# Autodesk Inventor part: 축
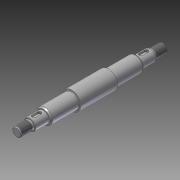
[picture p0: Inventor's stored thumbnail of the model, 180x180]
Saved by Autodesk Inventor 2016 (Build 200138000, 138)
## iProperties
Created: 2018-11
Part Number: 축
Material: 강철, 연강
Document SubType Name: Modeling
Designer: mduedu
Density: 1 g/cm^3
Appearance: 강철
Author: mduedu
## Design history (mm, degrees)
sketch "스케치1"
  geometry: L1 (-24, 0)-(24, 0); L2 (24, 0)-(24, 12); L3 (24, 12)-(-24, 12); L4 (-24, 12)-(-24, 0); L5 (-24, 0)-(-79, 0); L6 (-79, 0)-(-79, 7.5); L7 (-79, 7.5)-(-61, 7.5); L8 (-24, 7.5)-(-24, 0); L9 (-79, 0)-(-96, 0); L10 (-96, 0)-(-96, 6); L11 (-96, 6)-(-79, 6); L12 (-79, 6)-(-79, 0); L13 (0, 0)-(0, 12); L14 (24, 0)-(79, 0); L15 (79, 0)-(79, 7.5); L16 (79, 7.5)-(61, 7.5); L17 (24, 7.5)-(24, 0); L18 (79, 0)-(96, 0); L19 (96, 0)-(96, 6); L20 (96, 6)-(79, 6); L21 (79, 6)-(79, 0); L22 (-61, 7.5)-(-61, 8.85); L23 (-59.008, 10)-(-24, 10); L24 (24, 10)-(59.008, 10); L25 (61, 8.85)-(61, 7.5); L26 (-61, 8.85)-(-59.008, 10); L27 (61, 8.85)-(59.008, 10); 1 further point
  constraints: 54 end point, 9 parallel, 6 symmetric about line, 4 horizontal, 4 perpendicular, 2 midpoint, 2 point on line, 1 coincident
  dimensions: "d0" = 24 diameter of L3 L1; "d2" = 15 diameter of L7 L5; "d3" = 12 diameter of L11 L9; "d4" = 48 distance of L2.end L3.end; "d5" = 55 distance of L6.end L8.start; "d6" = 192 distance between parallel lines of L19 L10; "d24" = 20 diameter of L23 L5; "d25" = 18 distance of L6.end L7.end; "d26" = 18 distance of L15.end L16.end; "d27" = 20 diameter of L24 L14; "d28" = 55 distance between parallel lines of L15 L2; "d29" = 30 deg angle of L23 L26; "d30" = 17.7 diameter of L22.end L5; "d31" = 30 deg angle of L24 L27; "d32" = 17.7 diameter of L25.start L14
revolve "회전1" sketch "스케치1" stored, may be unused: angle "d7" = 90 deg
fillet "모깎기1" dims "d8" = 0.6
node "작업 평면1"
sketch "스케치2" dims "d11" = 12
  geometry: L1 (-3.5, 2.5)-(3.5, 2.5); L2 (3.5, 2.5)-(3.5, -2.5); L3 (3.5, -2.5)-(-3.5, -2.5); L4 (-3.5, -2.5)-(-3.5, 2.5); L5 (9, 7.5)-(9, -7.5) reference; 3 further points
  constraints: 8 end point, 2 midpoint, 2 parallel, 2 vertical alignment, 1 horizontal, 1 horizontal alignment, 1 perpendicular, 4 other
  dimensions: "d9" = 3 dimension on L5; "d10" = 5 distance between parallel lines of L3 L1
extrude "돌출1" cut sketch "스케치2" distance "d12" = 3; taper "d13" = 0 deg
chamfer "모따기1" distance "d14" = 0.5; stored, may be unused: second distance "d15" = 2, angle "d16" = 45 deg
feature "스레드1" dims "d17" = 15, "d18" = 0
feature "스레드2" dims "d19" = 15, "d20" = 0
chamfer "모따기2" distance "d21" = 1; stored, may be unused: second distance "d22" = 2, angle "d23" = 45 deg
node "솔리드1"
mirror "대칭1"
